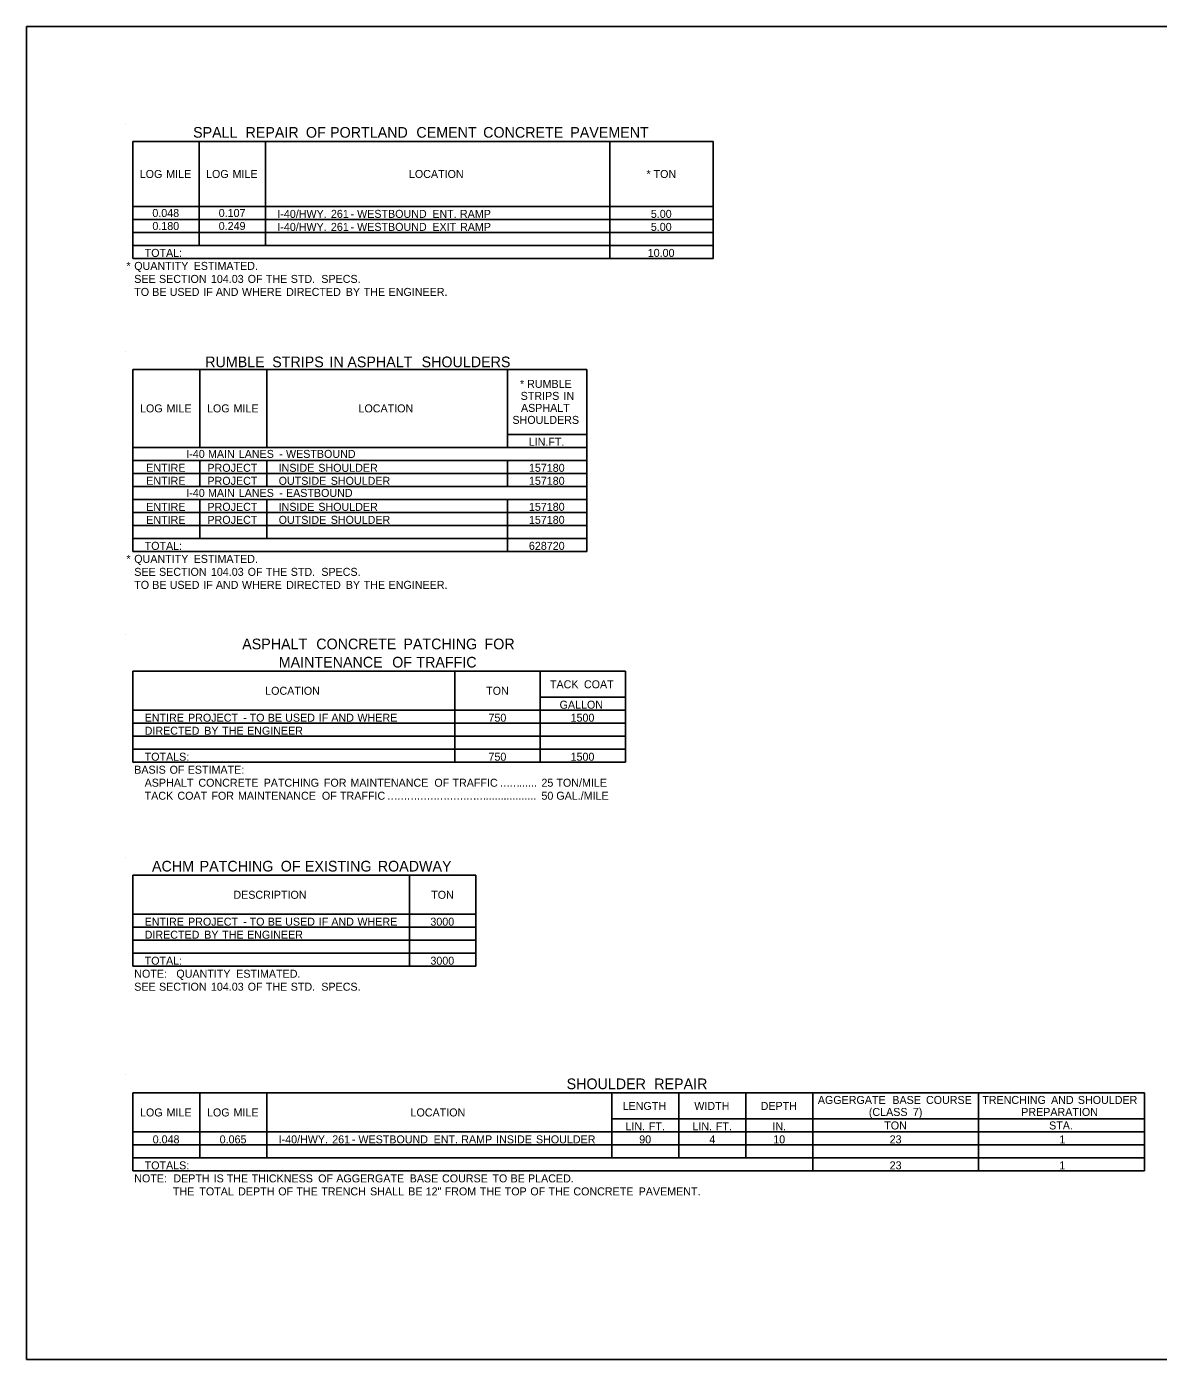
# Model space of a CAD drawing. Extents: x 2261867 to 2275370, y -3124789 to -3122260.
# Drawn here: x 2264290 to 2265138, y -3124774 to -3123775 of the extents above; entities that cross this region are included whole.
import ezdxf

# ---------------------------------------------------------------- set-up
doc = ezdxf.new("R2010")
doc.units = 0
for name, color, linetype in [('Default', 7, 'Continuous'), ('DSN_DRFT_Named-Boundary', 7, 'Continuous'), ('DSN_QNTY_Annotation', 7, 'Continuous')]:
    doc.layers.add(name, color=color, linetype=linetype)

msp = doc.modelspace()

# ---------------------------------------------------------------- linework, layer by layer
at = {"layer": 'Default'}
for p, q in [((2264363.85, -3123847.74), (2264363.85, -3123847.74)), ((2264363.85, -3124018.6), (2264363.85, -3124018.6)), ((2264363.85, -3124231.28), (2264363.85, -3124231.28)), ((2264363.85, -3124397.85), (2264363.85, -3124397.85)), ((2264363.85, -3124561.03), (2264363.85, -3124561.03))]:
    msp.add_line(p, q, dxfattribs=at)
at = {"layer": 'DSN_DRFT_Named-Boundary'}
msp.add_lwpolyline([(2264290.05, -3124774.39), (2265915.05, -3124774.39), (2265915.05, -3123775.33), (2264290.05, -3123775.33)], close=True, dxfattribs=at)
at = {"layer": 'DSN_QNTY_Annotation'}
for p, q in [((2264369.7, -3123861.39), (2264804.55, -3123861.39)), ((2264369.7, -3123949.14), (2264369.7, -3123861.39)), ((2264369.7, -3123949.14), (2264369.7, -3123861.39)), ((2264419.43, -3123939.39), (2264419.43, -3123861.39)), ((2264469.15, -3123939.39), (2264469.15, -3123861.39)), ((2264727.04, -3123949.14), (2264727.04, -3123861.39)), ((2264804.55, -3123949.14), (2264804.55, -3123861.39)), ((2264804.55, -3123949.14), (2264804.55, -3123861.39)), ((2264369.7, -3123910.14), (2264804.55, -3123910.14)), ((2264419.43, -3123939.39), (2264419.43, -3123910.14)), ((2264369.7, -3123919.89), (2264804.55, -3123919.89)), ((2264369.7, -3123929.64), (2264804.55, -3123929.64)), ((2264469.15, -3123939.39), (2264469.15, -3123929.64)), ((2264369.7, -3123939.39), (2264469.15, -3123939.39)), ((2264369.7, -3123939.39), (2264804.55, -3123939.39)), ((2264727.04, -3123949.14), (2264727.04, -3123939.39)), ((2264369.7, -3123949.14), (2264804.55, -3123949.14)), ((2264369.7, -3124032.25), (2264709.98, -3124032.25)), ((2264369.7, -3124168.75), (2264369.7, -3124032.25)), ((2264369.7, -3124168.75), (2264369.7, -3124032.25)), ((2264419.91, -3124090.75), (2264419.91, -3124032.25)), ((2264419.91, -3124090.75), (2264419.91, -3124032.25)), ((2264470.13, -3124090.75), (2264470.13, -3124032.25)), ((2264470.13, -3124090.75), (2264470.13, -3124032.25)), ((2264650.5, -3124090.75), (2264650.5, -3124032.25)), ((2264709.98, -3124168.75), (2264709.98, -3124032.25)), ((2264709.98, -3124081), (2264709.98, -3124032.25)), ((2264650.5, -3124081), (2264709.98, -3124081)), ((2264369.7, -3124090.75), (2264709.98, -3124090.75)), ((2264369.7, -3124090.75), (2264709.98, -3124090.75)), ((2264709.98, -3124100.5), (2264709.98, -3124090.75)), ((2264369.7, -3124100.5), (2264709.98, -3124100.5)), ((2264419.91, -3124120), (2264419.91, -3124100.5)), ((2264419.91, -3124120), (2264419.91, -3124100.5)), ((2264470.13, -3124120), (2264470.13, -3124100.5)), ((2264470.13, -3124120), (2264470.13, -3124100.5)), ((2264650.5, -3124120), (2264650.5, -3124100.5)), ((2264369.7, -3124110.25), (2264709.98, -3124110.25)), ((2264709.98, -3124120), (2264709.98, -3124110.25)), ((2264369.7, -3124120), (2264709.98, -3124120)), ((2264369.7, -3124120), (2264709.98, -3124120)), ((2264369.7, -3124129.75), (2264709.98, -3124129.75)), ((2264419.91, -3124159), (2264419.91, -3124129.75)), ((2264419.91, -3124159), (2264419.91, -3124129.75)), ((2264470.13, -3124129.75), (2264650.5, -3124129.75)), ((2264470.13, -3124159), (2264470.13, -3124129.75)), ((2264470.13, -3124159), (2264470.13, -3124129.75)), ((2264650.5, -3124168.75), (2264650.5, -3124129.75)), ((2264369.7, -3124139.5), (2264709.98, -3124139.5)), ((2264709.98, -3124168.75), (2264709.98, -3124139.5)), ((2264369.7, -3124149.25), (2264709.98, -3124149.25)), ((2264369.7, -3124159), (2264709.98, -3124159)), ((2264369.7, -3124159), (2264709.98, -3124159)), ((2264650.5, -3124168.75), (2264650.5, -3124159)), ((2264369.7, -3124168.75), (2264709.98, -3124168.75)), ((2264369.7, -3124258.58), (2264738.74, -3124258.58)), ((2264369.7, -3124326.83), (2264369.7, -3124258.58)), ((2264369.7, -3124326.83), (2264369.7, -3124258.58)), ((2264611.01, -3124326.83), (2264611.01, -3124258.58)), ((2264674.88, -3124326.83), (2264674.88, -3124258.58)), ((2264738.74, -3124326.83), (2264738.74, -3124258.58)), ((2264738.74, -3124278.08), (2264738.74, -3124258.58)), ((2264674.88, -3124278.08), (2264738.74, -3124278.08)), ((2264674.88, -3124326.83), (2264674.88, -3124278.08)), ((2264369.7, -3124287.83), (2264738.74, -3124287.83)), ((2264611.01, -3124326.83), (2264611.01, -3124287.83)), ((2264738.74, -3124307.33), (2264738.74, -3124287.83)), ((2264369.7, -3124297.58), (2264738.74, -3124297.58)), ((2264369.7, -3124307.33), (2264738.74, -3124307.33)), ((2264369.7, -3124317.08), (2264738.74, -3124317.08)), ((2264738.74, -3124326.83), (2264738.74, -3124317.08)), ((2264369.7, -3124326.83), (2264738.74, -3124326.83)), ((2264369.7, -3124411.5), (2264626.61, -3124411.5)), ((2264369.7, -3124479.75), (2264369.7, -3124411.5)), ((2264369.7, -3124479.75), (2264369.7, -3124411.5)), ((2264576.89, -3124479.75), (2264576.89, -3124411.5)), ((2264626.61, -3124479.75), (2264626.61, -3124411.5)), ((2264369.7, -3124440.75), (2264626.61, -3124440.75)), ((2264576.89, -3124479.75), (2264576.89, -3124440.75)), ((2264626.61, -3124479.75), (2264626.61, -3124440.75)), ((2264369.7, -3124450.5), (2264626.61, -3124450.5)), ((2264369.7, -3124460.25), (2264626.61, -3124460.25)), ((2264369.7, -3124470), (2264626.61, -3124470)), ((2264369.7, -3124479.75), (2264626.61, -3124479.75)), ((2264369.7, -3124574.68), (2265127.76, -3124574.68)), ((2264369.7, -3124633.18), (2264369.7, -3124574.68)), ((2264369.7, -3124633.18), (2264369.7, -3124574.68)), ((2264419.91, -3124623.43), (2264419.91, -3124574.68)), ((2264470.13, -3124623.43), (2264470.13, -3124574.68)), ((2264470.13, -3124623.43), (2264470.13, -3124574.68)), ((2264728.5, -3124623.43), (2264728.5, -3124574.68)), ((2264778.71, -3124623.43), (2264778.71, -3124574.68)), ((2264828.93, -3124623.43), (2264828.93, -3124574.68)), ((2264879.14, -3124633.18), (2264879.14, -3124574.68)), ((2265003.45, -3124633.18), (2265003.45, -3124574.68)), ((2265127.76, -3124633.18), (2265127.76, -3124574.68)), ((2265127.76, -3124633.18), (2265127.76, -3124574.68)), ((2264728.5, -3124594.18), (2265127.76, -3124594.18)), ((2264778.71, -3124603.93), (2264778.71, -3124594.18)), ((2264828.93, -3124603.93), (2264828.93, -3124594.18)), ((2264879.14, -3124603.93), (2264879.14, -3124594.18)), ((2264369.7, -3124603.93), (2265127.76, -3124603.93)), ((2264419.91, -3124623.43), (2264419.91, -3124603.93)), ((2264728.5, -3124603.93), (2264879.14, -3124603.93)), ((2264728.5, -3124623.43), (2264728.5, -3124603.93)), ((2264879.14, -3124603.93), (2265127.76, -3124603.93)), ((2264369.7, -3124613.68), (2265127.76, -3124613.68)), ((2264369.7, -3124623.43), (2265127.76, -3124623.43)), ((2264879.14, -3124623.43), (2265127.76, -3124623.43)), ((2264879.14, -3124633.18), (2264879.14, -3124623.43)), ((2264369.7, -3124633.18), (2265127.76, -3124633.18))]:
    msp.add_line(p, q, dxfattribs=at)

# ---------------------------------------------------------------- texts
for s, height, p in [('SPALL', 8, (2264414.78, -3123858.57)), (' REPAIR', 8, (2264451.09, -3123858.57)), (' OF', 8, (2264496.37, -3123858.57)), (' PORTLAND', 8, (2264514.48, -3123858.57)), (' CEMENT', 8, (2264579.14, -3123858.57)), (' CONCRETE', 8, (2264629.21, -3123858.57)), (' PAVEMENT', 8, (2264694.49, -3123858.57)), ('LOG', 6, (2264374.77, -3123888.77)), (' MILE', 6, (2264392.42, -3123888.77)), ('LOG', 6, (2264424.49, -3123888.77)), (' MILE', 6, (2264442.15, -3123888.77)), ('LOCATION', 6, (2264576.54, -3123888.77)), ('*', 6, (2264754.58, -3123888.77)), (' TON', 6, (2264757.66, -3123888.77)), ('0.048', 6, (2264384.26, -3123918.02)), ('0.107', 6, (2264433.99, -3123918.02)), ('0.180', 6, (2264384.28, -3123927.77)), ('0.249', 6, (2264433.99, -3123927.77)), ('I-40/HWY.', 6, (2264477.93, -3123918.69)), ('I-40/HWY.', 6, (2264477.93, -3123928.44)), (' 261', 6, (2264515.85, -3123918.69)), (' -', 6, (2264530.61, -3123918.69)), (' WESTBOUND', 6, (2264535.47, -3123918.69)), (' ENT.', 6, (2264591.85, -3123918.69)), (' RAMP', 6, (2264612.54, -3123918.69)), ('5.00', 6, (2264757.84, -3123918.69)), (' 261', 6, (2264515.85, -3123928.44)), (' -', 6, (2264530.61, -3123928.44)), (' WESTBOUND', 6, (2264535.47, -3123928.44)), (' EXIT', 6, (2264591.85, -3123928.44)), (' RAMP', 6, (2264612.64, -3123928.44)), ('5.00', 6, (2264757.84, -3123928.44)), ('TOTAL:', 6, (2264378.48, -3123947.94)), ('10.00', 6, (2264755.52, -3123947.94)), ('*', 6, (2264364.83, -3123957.69)), ('QUANTITY', 6, (2264370.68, -3123957.69)), (' ESTIMATED.', 6, (2264413, -3123957.69)), ('SEE', 6, (2264370.68, -3123967.44)), (' SECTION', 6, (2264387.01, -3123967.44)), (' 104.03', 6, (2264425.92, -3123967.44)), (' OF', 6, (2264453.49, -3123967.44)), (' THE', 6, (2264467.08, -3123967.44)), (' STD.', 6, (2264485.73, -3123967.44)), ('  SPECS.', 6, (2264506.42, -3123967.44)), ('TO', 6, (2264370.68, -3123977.19)), (' BE', 6, (2264381.94, -3123977.19)), (' USED', 6, (2264395.01, -3123977.19)), (' IF', 6, (2264420.19, -3123977.19)), (' AND', 6, (2264429.58, -3123977.19)), (' WHERE', 6, (2264449.16, -3123977.19)), (' DIRECTED', 6, (2264482.25, -3123977.19)), (' BY', 6, (2264526.98, -3123977.19)), (' THE', 6, (2264540.43, -3123977.19)), (' ENGINEER.', 6, (2264559.08, -3123977.19)), ('RUMBLE', 8, (2264423.84, -3124030.65)), (' STRIPS', 8, (2264471.11, -3124030.65)), (' IN', 8, (2264514.04, -3124030.65)), (' ASPHALT', 8, (2264527.42, -3124030.65)), (' SHOULDERS', 8, (2264583.09, -3124030.65)), ('*', 6, (2264659.81, -3124046.13)), (' RUMBLE', 6, (2264662.89, -3124046.13)), ('STRIPS', 6, (2264660.28, -3124055.13)), (' IN', 6, (2264690.16, -3124055.13)), ('LOG', 6, (2264375.01, -3124064.5)), (' MILE', 6, (2264392.67, -3124064.5)), ('LOG', 6, (2264425.22, -3124064.5)), (' MILE', 6, (2264442.88, -3124064.5)), ('LOCATION', 6, (2264538.76, -3124064.5)), ('ASPHALT', 6, (2264660.53, -3124064.13)), ('SHOULDERS', 6, (2264654.12, -3124073.13)), ('LIN.FT.', 6, (2264666.32, -3124089.55)), ('I-40', 6, (2264409.68, -3124098.63)), (' MAIN', 6, (2264423.7, -3124098.63)), (' LANES', 6, (2264446.78, -3124098.63)), (' -', 6, (2264477.11, -3124098.63)), (' WESTBOUND', 6, (2264482.17, -3124098.63)), ('ENTIRE', 6, (2264379.66, -3124109.05)), ('PROJECT', 6, (2264425.54, -3124109.05)), ('INSIDE', 6, (2264478.9, -3124109.05)), (' SHOULDER', 6, (2264506.4, -3124109.05)), ('157180', 6, (2264666.46, -3124109.05)), ('ENTIRE', 6, (2264379.66, -3124118.8)), ('I-40', 6, (2264409.68, -3124127.88)), ('PROJECT', 6, (2264425.54, -3124118.8)), (' MAIN', 6, (2264423.7, -3124127.88)), (' LANES', 6, (2264446.78, -3124127.88)), ('OUTSIDE', 6, (2264478.9, -3124118.8)), (' EASTBOUND', 6, (2264482.17, -3124127.88)), (' SHOULDER', 6, (2264515.72, -3124118.8)), ('157180', 6, (2264666.46, -3124118.8)), (' -', 6, (2264477.11, -3124127.88)), ('ENTIRE', 6, (2264379.66, -3124138.3)), ('PROJECT', 6, (2264425.54, -3124138.3)), ('PROJECT', 6, (2264425.54, -3124148.05)), ('OUTSIDE', 6, (2264478.9, -3124148.05)), ('INSIDE', 6, (2264478.9, -3124138.3)), (' SHOULDER', 6, (2264506.4, -3124138.3)), (' SHOULDER', 6, (2264515.72, -3124148.05)), ('157180', 6, (2264666.46, -3124138.3)), ('157180', 6, (2264666.46, -3124148.05)), ('ENTIRE', 6, (2264379.66, -3124148.05)), ('TOTAL:', 6, (2264378.48, -3124167.55)), ('628720', 6, (2264666.46, -3124167.55)), ('*', 6, (2264364.83, -3124177.3)), ('QUANTITY', 6, (2264370.68, -3124177.3)), (' ESTIMATED.', 6, (2264413, -3124177.3)), ('SEE', 6, (2264370.68, -3124187.05)), (' SECTION', 6, (2264387.01, -3124187.05)), (' 104.03', 6, (2264425.92, -3124187.05)), (' OF', 6, (2264453.49, -3124187.05)), (' THE', 6, (2264467.08, -3124187.05)), (' STD.', 6, (2264485.73, -3124187.05)), ('  SPECS.', 6, (2264506.42, -3124187.05)), ('TO', 6, (2264370.68, -3124196.8)), (' BE', 6, (2264381.94, -3124196.8)), (' USED', 6, (2264395.01, -3124196.8)), (' IF', 6, (2264420.19, -3124196.8)), (' AND', 6, (2264429.58, -3124196.8)), (' WHERE', 6, (2264449.16, -3124196.8)), (' DIRECTED', 6, (2264482.25, -3124196.8)), (' BY', 6, (2264526.98, -3124196.8)), (' THE', 6, (2264540.43, -3124196.8)), (' ENGINEER.', 6, (2264559.08, -3124196.8)), ('ASPHALT', 8, (2264451.57, -3124242.1)), (' CONCRETE', 8, (2264504.13, -3124242.1)), (' PATCHING', 8, (2264569.41, -3124242.1)), (' FOR', 8, (2264630.22, -3124242.1)), ('MAINTENANCE', 8, (2264478.97, -3124255.75)), (' OF', 8, (2264561.02, -3124255.75)), (' TRAFFIC', 8, (2264579.13, -3124255.75)), ('LOCATION', 6, (2264468.8, -3124276.2)), ('TON', 6, (2264634.43, -3124276.2)), ('TACK', 6, (2264682.22, -3124271.33)), (' COAT', 6, (2264705.49, -3124271.33)), ('GALLON', 6, (2264689.45, -3124286.63)), ('ENTIRE', 6, (2264378.48, -3124296.38)), (' PROJECT', 6, (2264408.77, -3124296.38)), (' TO', 6, (2264454.92, -3124296.38)), (' BE', 6, (2264468.52, -3124296.38)), (' USED', 6, (2264481.58, -3124296.38)), (' IF', 6, (2264506.76, -3124296.38)), (' AND', 6, (2264516.15, -3124296.38)), (' WHERE', 6, (2264535.73, -3124296.38)), ('750', 6, (2264636.16, -3124296.38)), ('1500', 6, (2264697.69, -3124296.38)), ('DIRECTED', 6, (2264378.48, -3124306.13)), (' BY', 6, (2264420.88, -3124306.13)), (' THE', 6, (2264434.33, -3124306.13)), (' -', 6, (2264450.06, -3124296.38)), (' ENGINEER', 6, (2264452.98, -3124306.13)), ('TOTALS:', 6, (2264378.48, -3124325.63)), ('750', 6, (2264636.16, -3124325.63)), ('1500', 6, (2264697.69, -3124325.63)), ('BASIS', 6, (2264370.68, -3124335.38)), (' OF', 6, (2264394.94, -3124335.38)), (' ESTIMATE:', 6, (2264408.52, -3124335.38)), ('ASPHALT', 6, (2264378.48, -3124345.13)), (' CONCRETE', 6, (2264416.52, -3124345.13)), (' PATCHING', 6, (2264465.44, -3124345.13)), (' FOR', 6, (2264510.57, -3124345.13)), (' MAINTENANCE', 6, (2264530.48, -3124345.13)), (' OF', 6, (2264593.38, -3124345.13)), (' TRAFFIC', 6, (2264606.97, -3124345.13)), ('25', 6, (2264675.85, -3124345.13)), (' TON/MILE', 6, (2264684.84, -3124345.13)), ('TACK', 6, (2264378.48, -3124354.88)), (' COAT', 6, (2264400.82, -3124354.88)), (' FOR', 6, (2264426.27, -3124354.88)), (' MAINTENANCE', 6, (2264446.18, -3124354.88)), (' OF', 6, (2264509.09, -3124354.88)), (' TRAFFIC', 6, (2264522.67, -3124354.88)), ('…', 6, (2264644.36, -3124345.13)), ('…', 6, (2264651.76, -3124345.13)), ('......', 6, (2264659.16, -3124345.13)), ('50', 6, (2264675.85, -3124354.88)), (' GAL./MILE', 6, (2264684.77, -3124354.88)), ('…', 6, (2264560.06, -3124354.88)), ('…', 6, (2264567.46, -3124354.88)), ('…', 6, (2264574.86, -3124354.88)), ('…', 6, (2264582.26, -3124354.88)), ('…', 6, (2264589.66, -3124354.88)), ('…', 6, (2264597.06, -3124354.88)), ('…', 6, (2264604.46, -3124354.88)), ('…', 6, (2264611.86, -3124354.88)), ('…', 6, (2264619.26, -3124354.88)), ('…', 6, (2264626.66, -3124354.88)), ('.................', 6, (2264634.06, -3124354.88)), ('ACHM', 8, (2264383.97, -3124408.68)), (' PATCHING', 8, (2264416.71, -3124408.68)), (' OF', 8, (2264477.51, -3124408.68)), (' EXISTING', 8, (2264495.62, -3124408.68)), (' ROADWAY', 8, (2264550.22, -3124408.68)), ('DESCRIPTION', 6, (2264444.98, -3124429.13)), ('TON', 6, (2264593.24, -3124429.13)), ('ENTIRE', 6, (2264378.48, -3124449.3)), (' PROJECT', 6, (2264408.77, -3124449.3)), (' -', 6, (2264450.06, -3124449.3)), (' TO', 6, (2264454.92, -3124449.3)), (' BE', 6, (2264468.52, -3124449.3)), (' USED', 6, (2264481.58, -3124449.3)), (' IF', 6, (2264506.76, -3124449.3)), (' AND', 6, (2264516.15, -3124449.3)), (' WHERE', 6, (2264535.73, -3124449.3)), ('3000', 6, (2264592.63, -3124449.3)), ('DIRECTED', 6, (2264378.48, -3124459.05)), (' BY', 6, (2264420.88, -3124459.05)), (' THE', 6, (2264434.33, -3124459.05)), (' ENGINEER', 6, (2264452.98, -3124459.05)), ('TOTAL:', 6, (2264378.48, -3124478.55)), ('3000', 6, (2264592.64, -3124478.55)), ('NOTE:', 6, (2264370.68, -3124488.3)), ('   QUANTITY', 6, (2264395.56, -3124488.3)), (' ESTIMATED.', 6, (2264444.87, -3124488.3)), ('SEE', 6, (2264370.68, -3124498.05)), (' SECTION', 6, (2264387.01, -3124498.05)), (' 104.03', 6, (2264425.92, -3124498.05)), (' OF', 6, (2264453.49, -3124498.05)), (' THE', 6, (2264467.08, -3124498.05)), (' STD.', 6, (2264485.73, -3124498.05)), ('  SPECS.', 6, (2264506.42, -3124498.05)), ('SHOULDER', 8, (2264694.75, -3124571.85)), (' REPAIR', 8, (2264757.43, -3124571.85)), ('LENGTH', 6, (2264736.7, -3124587.43)), ('WIDTH', 6, (2264790.41, -3124587.43)), ('DEPTH', 6, (2264840.15, -3124587.43)), ('AGGERGATE', 6, (2264882.99, -3124582.93)), (' BASE', 6, (2264936.61, -3124582.93)), (' COURSE', 6, (2264961.82, -3124582.93)), ('TRENCHING', 6, (2265006.24, -3124582.93)), (' AND', 6, (2265055.57, -3124582.93)), (' SHOULDER', 6, (2265075.64, -3124582.93)), ('LOG', 6, (2264375.01, -3124592.3)), (' MILE', 6, (2264392.67, -3124592.3)), ('LOG', 6, (2264425.22, -3124592.3)), (' MILE', 6, (2264442.88, -3124592.3)), ('LOCATION', 6, (2264577.76, -3124592.3)), ('(CLASS', 6, (2264921.23, -3124591.93)), (' 7)', 6, (2264952.02, -3124591.93)), ('PREPARATION', 6, (2265035.43, -3124591.93)), ('LIN.', 6, (2264738.82, -3124602.73)), (' FT.', 6, (2264754.07, -3124602.73)), ('LIN.', 6, (2264789.03, -3124602.73)), (' FT.', 6, (2264804.29, -3124602.73)), ('IN.', 6, (2264848.97, -3124602.73)), ('TON', 6, (2264932.78, -3124602.05)), ('STA.', 6, (2265056.35, -3124602.05)), ('0.048', 6, (2264384.51, -3124612.48)), ('0.065', 6, (2264434.7, -3124612.48)), ('I-40/HWY.', 6, (2264478.9, -3124612.48)), (' 261', 6, (2264516.82, -3124612.48)), (' -', 6, (2264531.59, -3124612.48)), (' WESTBOUND', 6, (2264536.45, -3124612.48)), (' ENT.', 6, (2264592.82, -3124612.48)), (' RAMP', 6, (2264613.52, -3124612.48)), (' INSIDE', 6, (2264639.7, -3124612.48)), (' SHOULDER', 6, (2264669.53, -3124612.48)), ('90', 6, (2264749.15, -3124612.48)), ('4', 6, (2264801.69, -3124612.48)), ('10', 6, (2264849.57, -3124612.48)), ('23', 6, (2264936.82, -3124612.48)), ('1', 6, (2265064.05, -3124612.48)), ('TOTALS:', 6, (2264378.48, -3124631.98)), ('23', 6, (2264936.82, -3124631.98)), ('1', 6, (2265063.96, -3124631.98)), ('NOTE:', 6, (2264370.68, -3124641.73)), ('  DEPTH', 6, (2264395.56, -3124641.73)), (' IS', 6, (2264427.96, -3124641.73)), (' THE', 6, (2264437.77, -3124641.73)), (' THICKNESS', 6, (2264456.42, -3124641.73)), (' OF', 6, (2264506.29, -3124641.73)), (' AGGERGATE', 6, (2264519.88, -3124641.73)), (' BASE', 6, (2264574.87, -3124641.73)), (' COURSE', 6, (2264599.12, -3124641.73)), (' TO', 6, (2264636.88, -3124641.73)), (' BE', 6, (2264650.47, -3124641.73)), (' PLACED.', 6, (2264663.54, -3124641.73)), ('             THE', 6, (2264370.68, -3124651.48)), (' TOTAL', 6, (2264417.26, -3124651.48)), (' DEPTH', 6, (2264446.31, -3124651.48)), (' OF', 6, (2264476.38, -3124651.48)), (' THE', 6, (2264489.96, -3124651.48)), (' TRENCH', 6, (2264508.61, -3124651.48)), (' SHALL', 6, (2264545.2, -3124651.48)), (' BE', 6, (2264573.79, -3124651.48)), (' 12"', 6, (2264586.85, -3124651.48)), (' FROM', 6, (2264601.09, -3124651.48)), (' THE', 6, (2264627.46, -3124651.48)), (' TOP', 6, (2264646.11, -3124651.48)), (' OF', 6, (2264665.31, -3124651.48)), (' THE', 6, (2264678.9, -3124651.48)), (' CONCRETE', 6, (2264697.55, -3124651.48)), (' PAVEMENT.', 6, (2264746.48, -3124651.48))]:
    msp.add_text(s, height=height, dxfattribs=at).set_placement(p)

doc.saveas('drawing.dxf')
